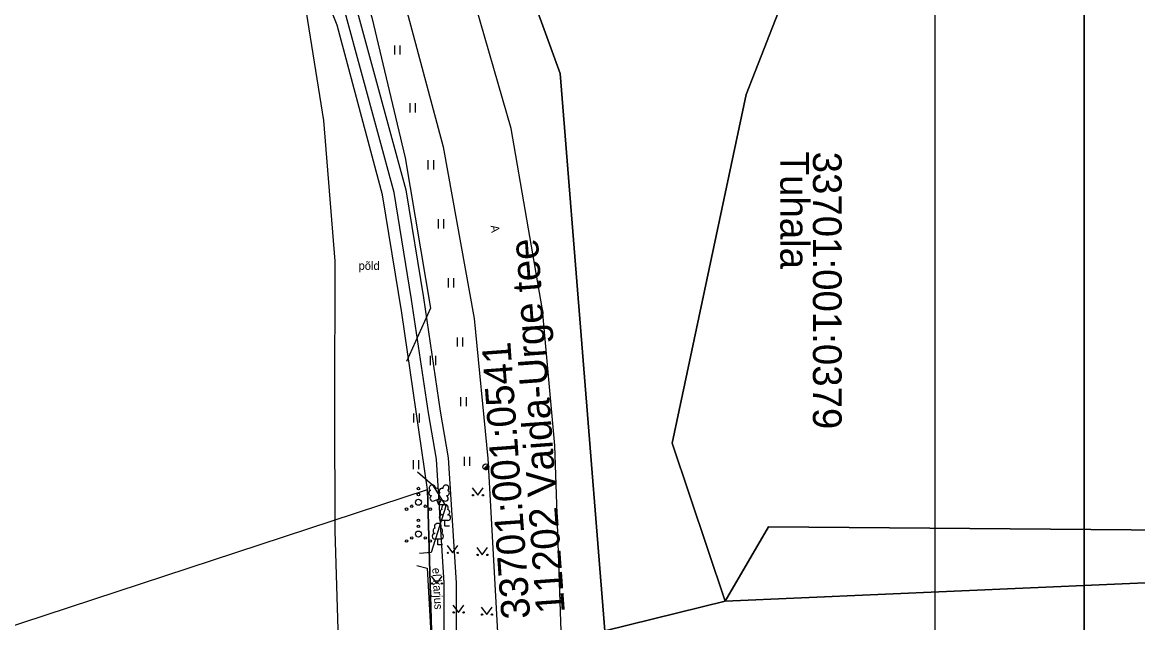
# Model space of a CAD drawing. Extents: x 554947 to 555436, y 6564938 to 6565792.
# Drawn here: x 555146.4 to 555239.7, y 6565295.3 to 6565345.5 of the extents above; entities that cross this region are included whole.
import ezdxf

# ---------------------------------------------------------------- set-up
doc = ezdxf.new("R2010")
doc.units = 0
for name, color, linetype in [('AED', 7, 'Continuous'), ('HALJASTUS', 7, 'Continuous'), ('KASUTUSALA', 7, 'Continuous'), ('KPKAABEL', 7, 'Continuous'), ('PIIR', 7, 'Continuous'), ('POST', 7, 'Continuous'), ('PR_SIDE', 7, 'Continuous'), ('PUU', 7, 'Continuous'), ('TEE', 7, 'Continuous'), ('VORMISTUS_1', 7, 'Continuous')]:
    doc.layers.add(name, color=color, linetype=linetype)

msp = doc.modelspace()

# ---------------------------------------------------------------- linework, layer by layer
at = {"layer": 'AED'}
msp.add_lwpolyline([(555179.37, 6565300.078), (555180.242, 6565299.846), (555180.75, 6565290.874), (555180.137, 6565280.616), (555178.982, 6565264.788), (555177.984, 6565255.288), (555177.306, 6565249.05), (555173.486, 6565227.422), (555169.733, 6565212.423), (555163.779, 6565189.534), (555156.086, 6565161.758), (555151.428, 6565143.905), (555146.995, 6565125.891), (555142.273, 6565107.514), (555136.767, 6565086.759), (555131.214, 6565064.984), (555128.386, 6565056.617), (555127.142, 6565056.522)], dxfattribs=at)
at = {"layer": 'HALJASTUS'}
for p, q in [((555177.507, 6565343.535), (555177.507, 6565342.774)), ((555177.962, 6565343.535), (555177.962, 6565342.774)), ((555178.792, 6565338.704), (555178.792, 6565337.943)), ((555179.247, 6565338.704), (555179.247, 6565337.943)), ((555180.298, 6565333.939), (555180.298, 6565333.178)), ((555180.753, 6565333.939), (555180.753, 6565333.178)), ((555181.143, 6565329.011), (555181.143, 6565328.25)), ((555181.598, 6565329.011), (555181.598, 6565328.25)), ((555181.988, 6565324.083), (555181.988, 6565323.322)), ((555182.443, 6565324.083), (555182.443, 6565323.322)), ((555182.744, 6565319.144), (555182.744, 6565318.383)), ((555183.199, 6565319.144), (555183.199, 6565318.383)), ((555180.486, 6565317.59), (555180.486, 6565316.829)), ((555180.941, 6565317.59), (555180.941, 6565316.829)), ((555183.038, 6565314.153), (555183.038, 6565313.392)), ((555183.493, 6565314.153), (555183.493, 6565313.392)), ((555179.108, 6565312.784), (555179.108, 6565312.023)), ((555179.563, 6565312.784), (555179.563, 6565312.023)), ((555179.069, 6565308.891), (555179.069, 6565308.13)), ((555179.524, 6565308.891), (555179.524, 6565308.13)), ((555183.331, 6565309.162), (555183.331, 6565308.401)), ((555183.786, 6565309.162), (555183.786, 6565308.401)), ((555184.008, 6565306.559), (555184.471, 6565305.953)), ((555184.471, 6565305.953), (555184.917, 6565306.559)), ((555181.901, 6565301.748), (555182.364, 6565301.141)), ((555182.364, 6565301.141), (555182.81, 6565301.748)), ((555184.386, 6565301.574), (555184.85, 6565300.967)), ((555184.85, 6565300.967), (555185.295, 6565301.574)), ((555180.571, 6565299.18), (555181.034, 6565298.573)), ((555181.034, 6565298.573), (555181.48, 6565299.18)), ((555182.395, 6565296.772), (555182.858, 6565296.166)), ((555182.858, 6565296.166), (555183.304, 6565296.772)), ((555184.765, 6565296.588), (555185.228, 6565295.981)), ((555185.228, 6565295.981), (555185.674, 6565296.588))]:
    msp.add_line(p, q, dxfattribs=at)
for points in [[(555147.437, 6565403.198), (555151.813, 6565400.39), (555156.402, 6565394.192), (555163.761, 6565377.834), (555172.39, 6565356.6), (555175.608, 6565345.88), (555178.387, 6565334.156), (555180.524, 6565321.581), (555178.521, 6565317.128)], [(555179.431, 6565307.904), (555180.696, 6565306.825), (555181.786, 6565305.035), (555180.57, 6565301.175), (555179.588, 6565301.089)]]:
    msp.add_lwpolyline(points, dxfattribs=at)
for centre, radius in [((555179.511, 6565306.513), 0.1), ((555179.511, 6565305.363), 0.25), ((555179.511, 6565306.013), 0.1), ((555184.07, 6565305.953), 0.055), ((555184.899, 6565305.953), 0.055), ((555178.511, 6565304.788), 0.1), ((555178.946, 6565305.038), 0.1), ((555180.076, 6565305.038), 0.1), ((555180.511, 6565304.788), 0.1), ((555179.511, 6565303.857), 0.1), ((555179.511, 6565302.707), 0.25), ((555179.511, 6565303.357), 0.1), ((555178.511, 6565302.132), 0.1), ((555178.946, 6565302.382), 0.1), ((555180.076, 6565302.382), 0.1), ((555180.511, 6565302.132), 0.1), ((555181.963, 6565301.141), 0.055), ((555182.792, 6565301.141), 0.055), ((555184.449, 6565300.967), 0.055), ((555185.277, 6565300.967), 0.055), ((555180.633, 6565298.573), 0.055), ((555181.462, 6565298.573), 0.055), ((555182.457, 6565296.166), 0.055), ((555183.286, 6565296.166), 0.055), ((555184.827, 6565295.981), 0.055), ((555185.656, 6565295.981), 0.055)]:
    msp.add_circle(centre, radius, dxfattribs=at)
at = {"layer": 'KASUTUSALA'}
for points in [[(555176.937, 6565240.135), (555179.22, 6565254.85), (555179.244, 6565255.16), (555179.541, 6565258.936), (555179.592, 6565259.587), (555180.41, 6565269.99), (555180.41, 6565269.99), (555180.41, 6565269.99), (555180.588, 6565278.069), (555180.8, 6565287.7), (555180.26, 6565306.43), (555178.11, 6565321.18), (555176.49, 6565331.05), (555172.72, 6565345.23), (555167.67, 6565357.913), (555166.64, 6565360.5), (555160.07, 6565375.54), (555144.16, 6565410.6), (555124.27, 6565454.45)], [(555126.773, 6565453.774), (555135.197, 6565435.201), (555141.868, 6565420.974), (555147.21, 6565409.597), (555154.633, 6565393.273), (555162.36, 6565375.334), (555168.957, 6565360.089), (555174.329, 6565346.596), (555178.447, 6565331.473), (555179.928, 6565322.45), (555181.326, 6565312.983), (555182.005, 6565309.084), (555182.652, 6565298.625), (555182.687, 6565282.55), (555182.408, 6565269.89), (555181.69, 6565260.757), (555194.028, 6565259.888), (555193.816, 6565257.898), (555181.571, 6565258.76), (555181.532, 6565258.735), (555181.208, 6565254.618), (555178.897, 6565239.723)]]:
    msp.add_lwpolyline(points, dxfattribs=at)
at = {"layer": 'KPKAABEL'}
msp.add_lwpolyline([(555126.894, 6565446.731), (555132.737, 6565435.388), (555136.366, 6565427.872), (555142.195, 6565415.637), (555145.001, 6565409.613), (555146.957, 6565405.365), (555152.799, 6565392.474), (555157.576, 6565380.671), (555161.529, 6565371.444), (555166.139, 6565359.889), (555169.783, 6565348.422), (555171.572, 6565337.25), (555172.523, 6565325.522), (555172.476, 6565313.268), (555172.511, 6565302.969), (555172.901, 6565290.135), (555172.887, 6565279.431), (555172.817, 6565266.938), (555172.536, 6565254.014), (555171.281, 6565241.464)], dxfattribs=at)
at = {"layer": 'PIIR'}
for points in [[(555393.069, 6565560.972), (555353.12, 6565523.87), (555343.14, 6565512.46), (555302.6, 6565539.71), (555242.37, 6565583.94), (555179.42, 6565586.32), (555138.98, 6565580.6), (555121.18, 6565602.26), (555116.17, 6565610.5), (555109.96, 6565624.83), (555093.56, 6565628.47), (555079.04, 6565618.4), (555074.13, 6565607.82), (555075.34, 6565593.24), (555091.74, 6565551.94), (555171.91, 6565394.64), (555191.35, 6565341.19), (555195.08, 6565294.61), (555195.28, 6565271.63), (555191.64, 6565237.48)], [(555153.01, 6565448.47), (555207.22, 6565406.57), (555216.83, 6565392.35), (555221.23, 6565376.06), (555206.9, 6565339.44), (555200.72, 6565310.3), (555205.15, 6565297.11), (555195.08, 6565294.61), (555191.35, 6565341.19), (555171.91, 6565394.64), (555091.74, 6565551.94)], [(555176.93, 6565240.09), (555179.22, 6565254.85), (555180.41, 6565269.99), (555180.8, 6565287.7), (555180.26, 6565306.43), (555178.11, 6565321.18), (555176.49, 6565331.05), (555172.72, 6565345.23), (555166.64, 6565360.5), (555160.07, 6565375.54), (555144.16, 6565410.6), (555124.27, 6565454.45)], [(555307.598, 6565160.101), (555289.11, 6565186.6), (555261.42, 6565218.27), (555255.75, 6565226.79), (555254.61, 6565228.5), (555256.63, 6565245.54), (555293.54, 6565286.23), (555292.52, 6565297.57), (555275.38, 6565300.17), (555205.15, 6565297.11), (555208.78, 6565303.3), (555303.13, 6565302.54), (555320.51, 6565314.61), (555338.117, 6565285.943)], [(555191.64, 6565237.48), (555195.28, 6565271.63), (555195.08, 6565294.61), (555205.15, 6565297.11), (555275.38, 6565300.17), (555292.52, 6565297.57), (555293.54, 6565286.23), (555256.63, 6565245.54)]]:
    msp.add_lwpolyline(points, dxfattribs=at)
for points in [[(555153.01, 6565448.47), (555161.15, 6565451.45), (555173.66, 6565456.03), (555207.29, 6565506.14), (555287.77, 6565518.56), (555302.6, 6565539.71), (555343.14, 6565512.46), (555319.44, 6565481.04), (555323.07, 6565461.26), (555312.9, 6565433.84), (555316.84, 6565372.52), (555318.72, 6565342.57), (555320.51, 6565314.61), (555303.13, 6565302.54), (555208.78, 6565303.3), (555205.15, 6565297.11), (555200.72, 6565310.3), (555206.9, 6565339.44), (555221.23, 6565376.06), (555216.83, 6565392.35), (555207.22, 6565406.57)], [(554962.55, 6565234.93), (555180.26, 6565306.43), (555180.8, 6565287.7), (555180.41, 6565269.99), (555179.22, 6565254.85), (555176.93, 6565240.09), (555172.7, 6565220.76), (555117.14, 6565008.97), (555108.27, 6564991.27)]]:
    msp.add_lwpolyline(points, close=True, dxfattribs=at)
at = {"layer": 'POST'}
msp.add_line((555184.97, 6565308.147), (555185.323, 6565308.5), dxfattribs=at)
msp.add_circle((555185.147, 6565308.323), 0.25, dxfattribs=at)
for radius, start, end in [(0.225, 224.85406, 45.03563), (0.2, 224.84272, 45.04698), (0.175, 224.82813, 45.06157), (0.15, 224.80867, 45.08103), (0.125, 224.78144, 45.10826), (0.1, 224.74058, 45.14911), (0.075, 224.67249, 45.2172), (0.05, 224.53632, 45.35338), (0.025, 224.12776, 45.76193)]:
    msp.add_arc((555185.147, 6565308.323), radius, start, end, dxfattribs=at)
at = {"layer": 'PR_SIDE'}
msp.add_lwpolyline([(555177.913, 6565239.906), (555180.214, 6565254.734), (555180.573, 6565259.307), (555181.409, 6565269.94), (555181.687, 6565282.56), (555181.652, 6565298.593), (555181.01, 6565308.967), (555180.338, 6565312.825), (555178.94, 6565322.296), (555177.469, 6565331.26), (555173.379, 6565346.279), (555168.033, 6565359.705), (555161.441, 6565374.938), (555153.718, 6565392.868), (555146.302, 6565409.177), (555140.964, 6565420.546), (555137.898, 6565426.982), (555134.288, 6565434.784), (555125.868, 6565453.349)], dxfattribs=at)
at = {"layer": 'PUU'}
for p, q in [((555180.785, 6565305.477), (555181.23, 6565305.652)), ((555181.225, 6565305.142), (555181.05, 6565305.582)), ((555181.225, 6565305.142), (555181.405, 6565305.582)), ((555181.23, 6565305.652), (555181.67, 6565305.472)), ((555181.605, 6565305.142), (555181.225, 6565305.142)), ((555181.963, 6565303.841), (555181.483, 6565303.841)), ((555181.723, 6565303.366), (555181.723, 6565303.841)), ((555182.103, 6565303.366), (555181.723, 6565303.366)), ((555181.369, 6565302.282), (555180.889, 6565302.282)), ((555181.129, 6565301.807), (555181.129, 6565302.282)), ((555181.509, 6565301.807), (555181.129, 6565301.807))]:
    msp.add_line(p, q, dxfattribs=at)
msp.add_lwpolyline([(555181.23, 6565306.147), (555181.21, 6565306.072), (555181.21, 6565306.052), (555181.22, 6565306.022), (555181.24, 6565305.987), (555181.245, 6565305.967), (555181.23, 6565305.932), (555181.205, 6565305.882), (555181.2, 6565305.857), (555181.205, 6565305.842), (555181.215, 6565305.812), (555181.25, 6565305.752), (555181.255, 6565305.732), (555181.25, 6565305.712), (555181.235, 6565305.677), (555181.23, 6565305.652)], dxfattribs=at)
for centre, radius, start, end in [((555180.668, 6565306.556), 0.256, 111.50269, 232.51731), ((555180.668, 6565306.556), 0.256, 350.48556, 111.50017), ((555181.002, 6565306.306), 0.224, 308.50412, 111.57247), ((555181.466, 6565306.301), 0.225, 67.7016, 230.51262), ((555181.804, 6565306.547), 0.256, 67.6168, 188.63142), ((555181.804, 6565306.547), 0.256, 306.59966, 67.61428), ((555180.594, 6565306.145), 0.224, 111.43041, 274.49868), ((555180.699, 6565305.7), 0.237, 111.50143, 291.50036), ((555181.229, 6565305.909), 0.237, 66.76552, 111.50149), ((555181.76, 6565305.692), 0.237, 247.61661, 67.61554), ((555181.871, 6565306.135), 0.224, 264.6183, 67.68657), ((555181.553, 6565304.539), 0.233, 109.02174, 253.14154), ((555181.723, 6565304.886), 0.277, 332.5799, 207.4201), ((555181.893, 6565304.539), 0.233, 286.85082, 70.98591), ((555181.486, 6565304.079), 0.238, 90.0016, 269.3953), ((555181.961, 6565304.079), 0.238, 270.6047, 89.9984), ((555180.959, 6565302.98), 0.233, 109.02174, 253.14154), ((555181.129, 6565303.327), 0.277, 332.5799, 207.4201), ((555181.299, 6565302.98), 0.233, 286.85082, 70.98591), ((555180.892, 6565302.52), 0.238, 90.0016, 269.3953), ((555181.367, 6565302.52), 0.238, 270.6047, 89.9984)]:
    msp.add_arc(centre, radius, start, end, dxfattribs=at)
at = {"layer": 'TEE'}
for points in [[(555190.709, 6565248.513), (555189.563, 6565248.443), (555190.146, 6565254.361), (555191.039, 6565262.566), (555191.617, 6565272.16), (555191.671, 6565280.957), (555191.452, 6565294.595), (555190.904, 6565310.102), (555189.89, 6565321.445), (555187.257, 6565336.603), (555183.958, 6565348.1), (555179.78, 6565359.387), (555170.643, 6565380.205), (555162.823, 6565397.349), (555156.491, 6565411.721), (555150.933, 6565424.006), (555146.697, 6565433.416), (555136.695, 6565455.531)], [(555131.266, 6565453.894), (555141.635, 6565431.431), (555145.957, 6565421.634), (555151.76, 6565408.809), (555158.151, 6565395.066), (555165.93, 6565378.047), (555174.733, 6565357.312), (555178.536, 6565346.409), (555181.58, 6565335.07), (555184.177, 6565320.727), (555185.301, 6565309.018), (555186.111, 6565294.522), (555186.299, 6565280.132), (555185.431, 6565263.333), (555184.399, 6565254.7), (555183.594, 6565248.995), (555179.697, 6565227.862)]]:
    msp.add_lwpolyline(points, dxfattribs=at)
at = {"layer": 'VORMISTUS_1'}
for points in [[(555045.188, 6565158.913), (555235.188, 6565158.913), (555235.188, 6565433.913), (555045.188, 6565433.913)], [(555045.188, 6565433.913), (555235.188, 6565433.913), (555235.188, 6565158.913), (555045.188, 6565158.913)], [(555222.688, 6565184.913), (555057.688, 6565184.913), (555057.688, 6565394.913), (555222.688, 6565394.913)]]:
    msp.add_lwpolyline(points, close=True, dxfattribs=at)

# ---------------------------------------------------------------- texts
at = {"layer": 'AED'}
msp.add_text('el karjus', height=0.7, rotation=273.19709, dxfattribs=at).set_placement((555180.661, 6565299.869))
at = {"layer": 'HALJASTUS'}
msp.add_text('põld', height=0.7, rotation=359.95437, dxfattribs=at).set_placement((555174.5, 6565324.781))
at = {"layer": 'PIIR'}
for s, rotation, p in [('Tuhala', 270, (555209.772, 6565334.663)), ('33701:001:0379', 270, (555212.495, 6565334.663)), ('11202 Vaida-Urge tee', 94.14867, (555191.757, 6565296.15)), ('33701:001:0541', 94.14867, (555188.866, 6565295.685))]:
    msp.add_text(s, height=2.4, rotation=rotation, dxfattribs=at).set_placement(p)
at = {"layer": 'TEE'}
msp.add_text('A', height=0.7, rotation=278.19181, dxfattribs=at).set_placement((555185.531, 6565328.477))

doc.saveas('drawing.dxf')
